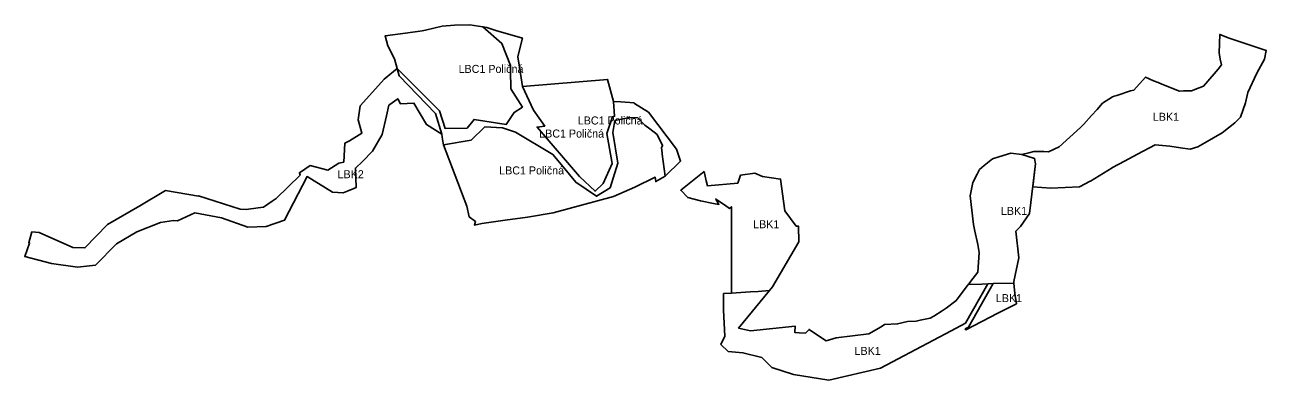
# Model space of a CAD drawing. Extents: x -502026 to -497556, y -1143322 to -1138019.
# Drawn here: x -500025 to -498783, y -1140842 to -1140487 of the extents above; entities that cross this region are included whole.
import ezdxf

# ---------------------------------------------------------------- set-up
doc = ezdxf.new("R2010")
doc.units = 0
for name, color, linetype in [('16', 7, 'Continuous'), ('17', 7, 'Continuous'), ('19', 7, 'Continuous'), ('20', 7, 'Continuous')]:
    doc.layers.add(name, color=color, linetype=linetype)

msp = doc.modelspace()

# ---------------------------------------------------------------- linework, layer by layer
at = {"layer": '16'}
msp.add_lwpolyline([(-499515.93, -1140572.31), (-499504.86, -1140588.13), (-499512.49, -1140589.17), (-499470.13, -1140638.41), (-499454.54, -1140653.33), (-499446.49, -1140645.45), (-499437.57, -1140625.52), (-499442.64, -1140595.64), (-499437.1, -1140578.87), (-499434.93, -1140578.4), (-499435.93, -1140563.57), (-499428.874, -1140564.055), (-499415.43, -1140564.98), (-499415.139, -1140565.67), (-499401.19, -1140574.18), (-499373.1, -1140611.24), (-499369.03, -1140623.13), (-499384.44, -1140638.12), (-499387.28, -1140616.19), (-499387.42, -1140614.8), (-499387.93, -1140609.82), (-499386.97, -1140607.49), (-499392.47, -1140596.44), (-499399.67, -1140591.011), (-499404.71, -1140587.21), (-499411.67, -1140580.09), (-499420.05, -1140579.58), (-499434.63, -1140582.68), (-499436.73, -1140594.59), (-499431.87, -1140625.18), (-499439.58, -1140649.75), (-499453.24, -1140658.22), (-499473.78, -1140644.22), (-499486.551, -1140628.729), (-499496.69, -1140616.43), (-499534.07, -1140594.13), (-499547.17, -1140590.03), (-499564.7, -1140588.95), (-499578.46, -1140602.36), (-499606.15, -1140606.98), (-499607.019, -1140601.544), (-499607.89, -1140596.1), (-499614.17, -1140575.64), (-499650.55, -1140537.99), (-499652.39, -1140530.78), (-499610.15, -1140572.87), (-499604.53, -1140590.48), (-499582.54, -1140590.43), (-499575.43, -1140581.51), (-499543.26, -1140586.53), (-499535.57, -1140574.57), (-499527.18, -1140569.27), (-499538.7, -1140550.93), (-499539.028, -1140532.751), (-499539.12, -1140527.68), (-499547.88, -1140505.67), (-499566.62, -1140489.06), (-499562.66, -1140489.67), (-499552.79, -1140493.24), (-499535.18, -1140498.15), (-499527.13, -1140500.39), (-499530.89, -1140514.69), (-499531.92, -1140519.15), (-499529.903, -1140531.205), (-499526.97, -1140548.74)], close=True, dxfattribs=at)
at = {"layer": '17'}
for points in [[(-499566.62, -1140489.06), (-499547.88, -1140505.67), (-499539.12, -1140527.68), (-499539.028, -1140532.751), (-499538.7, -1140550.93), (-499527.18, -1140569.27), (-499535.57, -1140574.57), (-499543.26, -1140586.53), (-499575.43, -1140581.51), (-499582.54, -1140590.43), (-499604.53, -1140590.48), (-499610.15, -1140572.87), (-499652.39, -1140530.78), (-499655.08, -1140521.18), (-499661.73, -1140508.09), (-499664.44, -1140498.01), (-499644.04, -1140495.57), (-499627.33, -1140493.08), (-499624.23, -1140492.57), (-499607.55, -1140488.51), (-499595.1, -1140487.47), (-499579.78, -1140487.14)], [(-499446.49, -1140645.45), (-499454.54, -1140653.33), (-499470.13, -1140638.41), (-499512.49, -1140589.17), (-499504.86, -1140588.13), (-499515.93, -1140572.31), (-499526.97, -1140548.74), (-499442, -1140541.58), (-499435.93, -1140563.57), (-499434.93, -1140578.4), (-499437.1, -1140578.87), (-499442.64, -1140595.64), (-499437.57, -1140625.52)], [(-499384.44, -1140638.12), (-499393.83, -1140643.64), (-499394.39, -1140639.31), (-499414.88, -1140649.23), (-499436.01, -1140658.54), (-499496.46, -1140674.88), (-499522.13, -1140678.98), (-499544.389, -1140682.197), (-499567.86, -1140685.59), (-499575.14, -1140687.01), (-499574, -1140683.5), (-499580.33, -1140678.85), (-499582.62, -1140668.25), (-499606.15, -1140606.98), (-499578.46, -1140602.36), (-499564.7, -1140588.95), (-499547.17, -1140590.03), (-499534.07, -1140594.13), (-499496.69, -1140616.43), (-499486.551, -1140628.729), (-499473.78, -1140644.22), (-499453.24, -1140658.22), (-499439.58, -1140649.75), (-499431.87, -1140625.18), (-499436.73, -1140594.59), (-499434.63, -1140582.68), (-499420.05, -1140579.58), (-499411.67, -1140580.09), (-499404.71, -1140587.21), (-499399.67, -1140591.011), (-499392.47, -1140596.44), (-499386.97, -1140607.49), (-499387.93, -1140609.82), (-499387.42, -1140614.8), (-499387.28, -1140616.19)]]:
    msp.add_lwpolyline(points, close=True, dxfattribs=at)
at = {"layer": '19'}
for points in [[(-498792.85, -1140535.36), (-498801.69, -1140554.56), (-498804.08, -1140565), (-498808.96, -1140579.4), (-498814.66, -1140584.99), (-498827.48, -1140595.03), (-498844.763, -1140604.989), (-498851.62, -1140608.94), (-498859.35, -1140611.25), (-498869.14, -1140609.91), (-498879.88, -1140608.33), (-498894.57, -1140606.97), (-498911.97, -1140616.22), (-498924.99, -1140623.14), (-498937.03, -1140629.54), (-498937.32, -1140629.72), (-498959.23, -1140643.29), (-498959.33, -1140643.34), (-498969.961, -1140648.733), (-498998.708, -1140650.243), (-499016.846, -1140648.693), (-499014.095, -1140625.974), (-499015.06, -1140620.53), (-499021.444, -1140618.517), (-499027.65, -1140616.56), (-499020.77, -1140614.83), (-499015.88, -1140613.49), (-499005.89, -1140613.67), (-499001.19, -1140613.75), (-498990.3, -1140608.8), (-498969.1, -1140589.77), (-498965.864, -1140586.199), (-498958.11, -1140577.64), (-498952.59, -1140571.55), (-498946.95, -1140565.32), (-498936.99, -1140558.93), (-498935.53, -1140558.45), (-498932.81, -1140557.55), (-498919.26, -1140553.08), (-498915.91, -1140552.5), (-498903.99, -1140539.28), (-498896.02, -1140542.85), (-498891.52, -1140544.61), (-498887.81, -1140546.48), (-498870.24, -1140553.24), (-498866.08, -1140553.12), (-498858.03, -1140552.89), (-498850.51, -1140550.01), (-498846.01, -1140548.29), (-498835.39, -1140536.01), (-498831.44, -1140531.44), (-498828.23, -1140527.09), (-498829.33, -1140521.23), (-498830.47, -1140515.09), (-498829.89, -1140496.72), (-498820.56, -1140500.53), (-498817.31, -1140501.5), (-498783.43, -1140512.69), (-498785.24, -1140521.55)], [(-499607.89, -1140596.1), (-499622.93, -1140586.62), (-499635.7, -1140565.22), (-499649.04, -1140566.11), (-499651.91, -1140560.85), (-499660.66, -1140567.43), (-499663.084, -1140577.886), (-499667.554, -1140596.698), (-499676.959, -1140613.373), (-499687.24, -1140623.4), (-499694.15, -1140630.16), (-499693.46, -1140649.66), (-499695.81, -1140650.61), (-499701.5, -1140652.85), (-499706.46, -1140654.8), (-499717.02, -1140654.21), (-499742.58, -1140638.53), (-499764.945, -1140682.012), (-499783.425, -1140688.312), (-499801.754, -1140689.017), (-499827.994, -1140679.907), (-499854.886, -1140674.725), (-499872.18, -1140682.78), (-499876.21, -1140682.41), (-499888.982, -1140684.337), (-499912.857, -1140693.632), (-499933.156, -1140705.742), (-499954.157, -1140726.953), (-499972.217, -1140729.053), (-499998.047, -1140725.483), (-500024.755, -1140718.454), (-500022.35, -1140711.62), (-500020.01, -1140704.98), (-500020.81, -1140704.65), (-500017.611, -1140693.867), (-500010.323, -1140694.441), (-499976.912, -1140709.54), (-499964.659, -1140709.748), (-499942.022, -1140686.487), (-499909.678, -1140667.909), (-499884.09, -1140652.58), (-499850.997, -1140658.006), (-499851.02, -1140657.801), (-499809.35, -1140671.27), (-499803.37, -1140671.37), (-499791.51, -1140669.73), (-499786.13, -1140668.98), (-499777.33, -1140663.14), (-499773.45, -1140660.56), (-499749.42, -1140637.35), (-499750.25, -1140634.76), (-499739.27, -1140627.68), (-499721.73, -1140632.13), (-499710.71, -1140625.11), (-499705.79, -1140624.12), (-499704.74, -1140605.17), (-499700.25, -1140603.05), (-499687.59, -1140595.41), (-499691.49, -1140581.95), (-499689.41, -1140567.81), (-499686.19, -1140564.29), (-499665.39, -1140541.51), (-499652.39, -1140530.78), (-499650.55, -1140537.99), (-499614.17, -1140575.64)], [(-499244.07, -1140795.09), (-499240.55, -1140791.12), (-499225.11, -1140801.48), (-499223.53, -1140802.54), (-499213.58, -1140799.48), (-499180.73, -1140795.76), (-499168.58, -1140788.47), (-499165.14, -1140786.36), (-499152.04, -1140785.71), (-499142.03, -1140783.15), (-499133.53, -1140782.8), (-499129.46, -1140781.97), (-499119.38, -1140779.92), (-499115.76, -1140777.81), (-499107.58, -1140772.51), (-499103.47, -1140769.84), (-499093.62, -1140762.66), (-499091.98, -1140760.5), (-499081.3, -1140746.44), (-499067.685, -1140745.918), (-499061.682, -1140745.688), (-499084.18, -1140784.93), (-499098.45, -1140792.47), (-499169.08, -1140829.79), (-499220.72, -1140841.83), (-499256.21, -1140836.16), (-499277.72, -1140829.32), (-499287.7, -1140819.38), (-499306.66, -1140814.44), (-499321.543, -1140813.204), (-499328.65, -1140806.13), (-499324.82, -1140798.07), (-499326.096, -1140771.914), (-499325.955, -1140755.459), (-499318.205, -1140754.864), (-499299.376, -1140753.677), (-499291.492, -1140753.18), (-499280.121, -1140752.464), (-499311.03, -1140789.86), (-499299.02, -1140792.7), (-499254.28, -1140788.04), (-499254.78, -1140794.22), (-499250.4, -1140794.57)], [(-499056.3, -1140745.482), (-499035.689, -1140744.86), (-499034.62, -1140755.24), (-499032.97, -1140765.49), (-499051.81, -1140775.1), (-499083.85, -1140791.45), (-499084.32, -1140790.665), (-499080.97, -1140788.98)]]:
    msp.add_lwpolyline(points, close=True, dxfattribs=at)
at = {"layer": '20'}
for points in [[(-499067.685, -1140745.918), (-499081.3, -1140746.44), (-499080.879, -1140745.886), (-499079.831, -1140744.505), (-499076.35, -1140739.92), (-499071.9, -1140734.07), (-499070.28, -1140714.4), (-499071.93, -1140706.5), (-499074.73, -1140693.14), (-499076.12, -1140686.47), (-499079.52, -1140657.94), (-499076.87, -1140644.51), (-499072.58, -1140636.22), (-499070.17, -1140631.57), (-499065.36, -1140627.7), (-499056.95, -1140620.92), (-499050.8, -1140618.95), (-499038.79, -1140615.12), (-499027.65, -1140616.56), (-499021.444, -1140618.517), (-499015.06, -1140620.53), (-499014.095, -1140625.974), (-499020.1, -1140675.56), (-499029, -1140688.61), (-499033.93, -1140693.11), (-499030.81, -1140719.88), (-499035.84, -1140743.39), (-499035.689, -1140744.86), (-499056.3, -1140745.482), (-499061.682, -1140745.688)], [(-499343.34, -1140642.72), (-499342.17, -1140647.8), (-499311.8, -1140645.11), (-499309.22, -1140637.3), (-499294.64, -1140635.04), (-499287.15, -1140638.53), (-499268.97, -1140641.12), (-499264.63, -1140672.68), (-499253.41, -1140688.26), (-499251.1, -1140688), (-499250.63, -1140703.66), (-499277.06, -1140748.76), (-499280.121, -1140752.464), (-499291.492, -1140753.18), (-499299.376, -1140753.677), (-499318.205, -1140754.864), (-499318.17, -1140668.78), (-499320.15, -1140670.38), (-499325.18, -1140666.98), (-499333.87, -1140661.11), (-499330.61, -1140666.33), (-499336.17, -1140665.33), (-499348.98, -1140662.77), (-499361.92, -1140659.52), (-499368.85, -1140652.22), (-499345.45, -1140633.59)]]:
    msp.add_lwpolyline(points, close=True, dxfattribs=at)

# ---------------------------------------------------------------- texts
at = {"layer": '16'}
msp.add_text('LBC1 Poličná', height=8, dxfattribs=at).set_placement((-499510.378, -1140599.647))
at = {"layer": '17'}
for p in [(-499590.966, -1140535.119), (-499471.793, -1140586.607), (-499550.39, -1140636.457)]:
    msp.add_text('LBC1 Poličná', height=8, dxfattribs=at).set_placement(p)
at = {"layer": '19'}
for s, p in [('LBK1', (-498896.705, -1140582.926)), ('LBK2', (-499711.966, -1140640.236)), ('LBK1', (-499053.707, -1140763.949)), ('LBK1', (-499195.025, -1140816.629))]:
    msp.add_text(s, height=8, dxfattribs=at).set_placement(p)
at = {"layer": '20'}
for p in [(-499048.648, -1140676.879), (-499296.44, -1140690.147)]:
    msp.add_text('LBK1', height=8, dxfattribs=at).set_placement(p)

doc.saveas('drawing.dxf')
